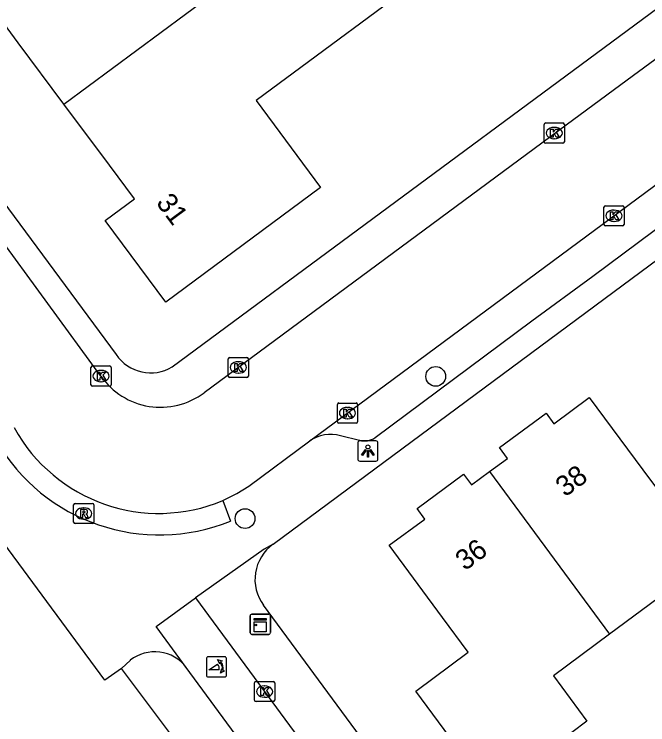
# Model space of a CAD drawing. Extents: x 163427 to 164190, y 380331 to 381641.
# Drawn here: x 163827.17 to 163858.59, y 381170.43 to 381205.64 of the extents above; entities that cross this region are included whole.
import ezdxf

# ---------------------------------------------------------------- set-up
doc = ezdxf.new("R2010")
doc.units = 0
for name, color, linetype in [('IMGEO_Boom', 7, 'Continuous'), ('IMGEO_Fietspad_open', 7, 'Continuous'), ('IMGEO_Groenvoorziening', 7, 'Continuous'), ('IMGEO_Kast', 7, 'Continuous'), ('IMGEO_Kolk', 7, 'Continuous'), ('IMGEO_Lichtpunt', 7, 'Continuous'), ('IMGEO_Pand', 7, 'Continuous'), ('IMGEO_Pand_nummerreeks', 7, 'Continuous'), ('IMGEO_Poller', 7, 'Continuous'), ('IMGEO_Rijbaan_lokaal_open', 7, 'Continuous'), ('IMGEO_Rioolput', 7, 'Continuous'), ('IMGEO_Voetpad_open', 7, 'Continuous')]:
    doc.layers.add(name, color=color, linetype=linetype)

msp = doc.modelspace()

# ---------------------------------------------------------------- linework, layer by layer
at = {"layer": 'IMGEO_Boom'}
for centre in [(163848.072, 381187.697), (163838.62, 381180.647)]:
    msp.add_circle(centre, 0.489, dxfattribs=at)
at = {"layer": 'IMGEO_Fietspad_open'}
for points in [[(163835.703, 381173.277), (163834.212, 381175.298), (163836.166, 381176.725)], [(163836.166, 381176.725), (163851.72, 381155.614), (163849.785, 381154.173), (163848.55, 381155.876)], [(163839.548, 381168.029), (163835.703, 381173.277)]]:
    msp.add_lwpolyline(points, dxfattribs=at)
at = {"layer": 'IMGEO_Groenvoorziening'}
msp.add_lwpolyline([(163837.499, 381166.547), (163832.5, 381173.217)], dxfattribs=at)
at = {"layer": 'IMGEO_Kast'}
for p, q in [((163838.949, 381175.912), (163839.79, 381175.912)), ((163839.79, 381175.912), (163838.949, 381175.912)), ((163838.874, 381174.987), (163838.874, 381175.828)), ((163838.874, 381175.828), (163838.874, 381174.987)), ((163839.874, 381175.837), (163839.874, 381174.996)), ((163839.874, 381174.996), (163839.874, 381175.837)), ((163839.799, 381174.912), (163838.958, 381174.912)), ((163838.958, 381174.912), (163839.799, 381174.912))]:
    msp.add_line(p, q, dxfattribs=at)
for points in [[(163839.069, 381175.702), (163839.669, 381175.702), (163839.669, 381175.617), (163839.069, 381175.617), (163839.069, 381175.702)], [(163839.069, 381175.527), (163839.669, 381175.527), (163839.669, 381175.038), (163839.069, 381175.038), (163839.069, 381175.527)]]:
    msp.add_lwpolyline(points, dxfattribs=at)
msp.add_circle((163839.153, 381175.376), 0.0377, dxfattribs=at)
for centre, start, end in [((163838.952, 381175.834), 92.4484, 184.2845), ((163838.952, 381175.834), 92.4484, 184.2845), ((163839.796, 381175.834), 2.4484, 94.2845), ((163839.796, 381175.834), 2.4484, 94.2845), ((163838.952, 381174.99), 182.4484, 274.2845), ((163838.952, 381174.99), 182.4484, 274.2845), ((163839.796, 381174.99), 272.4484, 4.2845), ((163839.796, 381174.99), 272.4484, 4.2845)]:
    msp.add_arc(centre, 0.0779, start, end, dxfattribs=at)
at = {"layer": 'IMGEO_Kolk'}
for p, q in [((163853.451, 381199.328), (163853.451, 381200.18)), ((163853.526, 381200.254), (163854.378, 381200.254)), ((163854.452, 381200.18), (163854.452, 381199.328)), ((163853.939, 381200.034), (163853.964, 381200.034)), ((163853.962, 381199.474), (163853.937, 381199.474)), ((163854.378, 381199.254), (163853.526, 381199.254)), ((163856.413, 381195.229), (163856.413, 381196.081)), ((163856.488, 381196.155), (163857.34, 381196.155)), ((163857.414, 381196.081), (163857.414, 381195.229)), ((163856.901, 381195.935), (163856.926, 381195.935)), ((163856.924, 381195.375), (163856.899, 381195.375)), ((163857.34, 381195.155), (163856.488, 381195.155)), ((163837.785, 381187.714), (163837.785, 381188.566)), ((163837.86, 381188.64), (163838.712, 381188.64)), ((163838.786, 381188.566), (163838.786, 381187.714)), ((163831.052, 381188.211), (163831.904, 381188.211)), ((163838.273, 381188.42), (163838.298, 381188.42)), ((163830.977, 381187.285), (163830.977, 381188.137)), ((163831.465, 381187.991), (163831.49, 381187.991)), ((163831.978, 381188.137), (163831.978, 381187.285)), ((163838.296, 381187.86), (163838.271, 381187.86)), ((163838.712, 381187.64), (163837.86, 381187.64)), ((163831.904, 381187.211), (163831.052, 381187.211)), ((163831.488, 381187.431), (163831.463, 381187.431)), ((163843.196, 381185.451), (163843.196, 381186.303)), ((163843.271, 381186.377), (163844.123, 381186.377)), ((163843.684, 381186.157), (163843.709, 381186.157)), ((163844.197, 381186.303), (163844.197, 381185.451)), ((163844.123, 381185.377), (163843.271, 381185.377)), ((163843.707, 381185.597), (163843.682, 381185.597)), ((163839.087, 381171.652), (163839.087, 381172.504)), ((163839.162, 381172.578), (163840.014, 381172.578)), ((163839.575, 381172.358), (163839.6, 381172.358)), ((163840.088, 381172.504), (163840.088, 381171.652)), ((163839.598, 381171.798), (163839.573, 381171.798)), ((163840.014, 381171.578), (163839.162, 381171.578))]:
    msp.add_line(p, q, dxfattribs=at)
for points in [[(163853.451, 381199.328), (163853.451, 381200.18)], [(163853.526, 381200.254), (163854.378, 381200.254)], [(163854.452, 381200.18), (163854.452, 381199.328)], [(163853.772, 381199.954), (163853.895, 381199.954), (163853.895, 381199.803), (163854.025, 381199.954), (163854.189, 381199.954), (163854.043, 381199.803), (163854.196, 381199.554), (163854.044, 381199.554), (163853.959, 381199.718), (163853.895, 381199.651), (163853.895, 381199.554), (163853.772, 381199.554), (163853.772, 381199.954)], [(163854.378, 381199.254), (163853.526, 381199.254)], [(163856.413, 381195.229), (163856.413, 381196.081)], [(163856.488, 381196.155), (163857.34, 381196.155)], [(163857.414, 381196.081), (163857.414, 381195.229)], [(163856.734, 381195.855), (163856.857, 381195.855), (163856.857, 381195.704), (163856.987, 381195.855), (163857.151, 381195.855), (163857.005, 381195.704), (163857.158, 381195.455), (163857.006, 381195.455), (163856.921, 381195.619), (163856.857, 381195.552), (163856.857, 381195.455), (163856.734, 381195.455), (163856.734, 381195.855)], [(163857.34, 381195.155), (163856.488, 381195.155)], [(163837.785, 381187.714), (163837.785, 381188.566)], [(163837.86, 381188.64), (163838.712, 381188.64)], [(163838.786, 381188.566), (163838.786, 381187.714)], [(163831.052, 381188.211), (163831.904, 381188.211)], [(163838.106, 381188.34), (163838.229, 381188.34), (163838.229, 381188.189), (163838.359, 381188.34), (163838.523, 381188.34), (163838.377, 381188.189), (163838.53, 381187.94), (163838.378, 381187.94), (163838.293, 381188.104), (163838.229, 381188.037), (163838.229, 381187.94), (163838.106, 381187.94), (163838.106, 381188.34)], [(163830.977, 381187.285), (163830.977, 381188.137)], [(163831.298, 381187.911), (163831.421, 381187.911), (163831.421, 381187.76), (163831.551, 381187.911), (163831.715, 381187.911), (163831.569, 381187.76), (163831.722, 381187.511), (163831.57, 381187.511), (163831.485, 381187.675), (163831.421, 381187.608), (163831.421, 381187.511), (163831.298, 381187.511), (163831.298, 381187.911)], [(163831.978, 381188.137), (163831.978, 381187.285)], [(163838.712, 381187.64), (163837.86, 381187.64)], [(163831.904, 381187.211), (163831.052, 381187.211)], [(163843.196, 381185.451), (163843.196, 381186.303)], [(163843.271, 381186.377), (163844.123, 381186.377)], [(163844.197, 381186.303), (163844.197, 381185.451)], [(163843.517, 381186.077), (163843.64, 381186.077), (163843.64, 381185.926), (163843.77, 381186.077), (163843.934, 381186.077), (163843.788, 381185.926), (163843.941, 381185.677), (163843.789, 381185.677), (163843.704, 381185.841), (163843.64, 381185.774), (163843.64, 381185.677), (163843.517, 381185.677), (163843.517, 381186.077)], [(163844.123, 381185.377), (163843.271, 381185.377)], [(163839.087, 381171.652), (163839.087, 381172.504)], [(163839.162, 381172.578), (163840.014, 381172.578)], [(163840.088, 381172.504), (163840.088, 381171.652)], [(163839.408, 381172.278), (163839.531, 381172.278), (163839.531, 381172.127), (163839.661, 381172.278), (163839.825, 381172.278), (163839.679, 381172.127), (163839.832, 381171.878), (163839.68, 381171.878), (163839.595, 381172.042), (163839.531, 381171.975), (163839.531, 381171.878), (163839.408, 381171.878), (163839.408, 381172.278)], [(163840.014, 381171.578), (163839.162, 381171.578)]]:
    msp.add_lwpolyline(points, dxfattribs=at)
for centre, start, end in [((163853.528, 381200.178), 91.552, 178.448), ((163853.528, 381200.178), 91.552, 178.448), ((163854.376, 381200.178), 1.552, 88.448), ((163854.376, 381200.178), 1.552, 88.448), ((163853.528, 381199.33), 181.552, 268.448), ((163853.528, 381199.33), 181.552, 268.448), ((163854.376, 381199.33), 271.552, 358.448), ((163854.376, 381199.33), 271.552, 358.448), ((163856.49, 381196.079), 91.552, 178.448), ((163856.49, 381196.079), 91.552, 178.448), ((163857.338, 381196.079), 1.552, 88.448), ((163857.338, 381196.079), 1.552, 88.448), ((163856.49, 381195.231), 181.552, 268.448), ((163856.49, 381195.231), 181.552, 268.448), ((163857.338, 381195.231), 271.552, 358.448), ((163857.338, 381195.231), 271.552, 358.448), ((163837.862, 381188.564), 91.552, 178.448), ((163837.862, 381188.564), 91.552, 178.448), ((163838.71, 381188.564), 1.552, 88.448), ((163838.71, 381188.564), 1.552, 88.448), ((163831.054, 381188.135), 91.552, 178.448), ((163831.054, 381188.135), 91.552, 178.448), ((163831.902, 381188.135), 1.552, 88.448), ((163831.902, 381188.135), 1.552, 88.448), ((163837.862, 381187.716), 181.552, 268.448), ((163837.862, 381187.716), 181.552, 268.448), ((163838.71, 381187.716), 271.552, 358.448), ((163838.71, 381187.716), 271.552, 358.448), ((163831.054, 381187.287), 181.552, 268.448), ((163831.054, 381187.287), 181.552, 268.448), ((163831.902, 381187.287), 271.552, 358.448), ((163831.902, 381187.287), 271.552, 358.448), ((163843.273, 381186.301), 91.552, 178.448), ((163843.273, 381186.301), 91.552, 178.448), ((163844.121, 381186.301), 1.552, 88.448), ((163844.121, 381186.301), 1.552, 88.448), ((163843.273, 381185.453), 181.552, 268.448), ((163843.273, 381185.453), 181.552, 268.448), ((163844.121, 381185.453), 271.552, 358.448), ((163844.121, 381185.453), 271.552, 358.448), ((163839.164, 381172.502), 91.552, 178.448), ((163839.164, 381172.502), 91.552, 178.448), ((163840.012, 381172.502), 1.552, 88.448), ((163840.012, 381172.502), 1.552, 88.448), ((163839.164, 381171.654), 181.552, 268.448), ((163839.164, 381171.654), 181.552, 268.448), ((163840.012, 381171.654), 271.552, 358.448), ((163840.012, 381171.654), 271.552, 358.448)]:
    msp.add_arc(centre, 0.0765, start, end, dxfattribs=at)
for centre, major_axis, ratio, start_param, end_param in [((163853.938, 381199.754), (-0.387, 0.002), 0.722429, 4.712389, 7.853982), ((163853.963, 381199.754), (-0.39, 0.002), 0.717154, 1.570796, 4.712389), ((163856.9, 381195.655), (-0.387, 0.002), 0.722429, 4.712389, 7.853982), ((163856.925, 381195.655), (-0.39, 0.002), 0.717154, 1.570796, 4.712389), ((163838.272, 381188.14), (-0.387, 0.002), 0.722429, 4.712389, 7.853982), ((163838.297, 381188.14), (-0.39, 0.002), 0.717154, 1.570796, 4.712389), ((163831.464, 381187.711), (-0.387, 0.002), 0.722429, 4.712389, 7.853982), ((163831.489, 381187.711), (-0.39, 0.002), 0.717154, 1.570796, 4.712389), ((163843.683, 381185.877), (-0.387, 0.002), 0.722429, 4.712389, 7.853982), ((163843.708, 381185.877), (-0.39, 0.002), 0.717154, 1.570796, 4.712389), ((163839.574, 381172.078), (-0.387, 0.002), 0.722429, 4.712389, 7.853982), ((163839.599, 381172.078), (-0.39, 0.002), 0.717154, 1.570796, 4.712389)]:
    msp.add_ellipse(centre, major_axis=major_axis, ratio=ratio, start_param=start_param, end_param=end_param, dxfattribs=at)
at = {"layer": 'IMGEO_Lichtpunt'}
for p, q in [((163844.21, 381184.403), (163844.21, 381183.596)), ((163844.21, 381184.403), (163844.21, 381183.596)), ((163845.112, 381184.498), (163844.304, 381184.498)), ((163845.112, 381184.498), (163844.304, 381184.498)), ((163845.206, 381183.596), (163845.206, 381184.403)), ((163845.206, 381183.596), (163845.206, 381184.403)), ((163844.304, 381183.502), (163845.112, 381183.502)), ((163844.304, 381183.502), (163845.112, 381183.502))]:
    msp.add_line(p, q, dxfattribs=at)
for points in [[(163844.584, 381184.067), (163844.623, 381184.039), (163844.435, 381183.777), (163844.397, 381183.804), (163844.584, 381184.067)], [(163844.686, 381184.019), (163844.733, 381184.019), (163844.733, 381183.697), (163844.686, 381183.697), (163844.686, 381184.019)], [(163844.796, 381184.039), (163844.834, 381184.066), (163845.021, 381183.804), (163844.982, 381183.776), (163844.796, 381184.039)]]:
    msp.add_lwpolyline(points, dxfattribs=at)
msp.add_circle((163844.709, 381184.201), 0.0994, dxfattribs=at)
for centre, start, end in [((163844.304, 381184.403), 90, 180), ((163844.304, 381184.403), 90, 180), ((163845.112, 381184.403), 0, 90), ((163845.112, 381184.403), 0, 90), ((163844.304, 381183.596), 180, 270), ((163844.304, 381183.596), 180, 270), ((163845.112, 381183.596), 270, 0), ((163845.112, 381183.596), 270, 360)]:
    msp.add_arc(centre, 0.0946, start, end, dxfattribs=at)
at = {"layer": 'IMGEO_Pand'}
for points in [[(163829.636, 381201.19), (163845.311, 381212.802)], [(163829.636, 381201.19), (163827.371, 381204.23), (163826.126, 381205.901), (163824.687, 381204.828), (163821.686, 381208.868), (163823.131, 381209.94)], [(163848.469, 381208.26), (163839.171, 381201.361), (163842.364, 381197.057), (163834.696, 381191.367), (163831.69, 381195.418), (163833.135, 381196.495), (163831.894, 381198.16), (163829.636, 381201.19)], [(163850.738, 381182.979), (163851.626, 381183.634), (163851.233, 381184.167), (163853.543, 381185.871), (163853.934, 381185.345), (163855.687, 381186.647), (163858.342, 381183.072), (163859.609, 381181.366), (163862.19, 381183.282), (163863.904, 381180.962), (163865.905, 381178.254), (163861.144, 381174.732), (163859.481, 381176.98), (163856.695, 381174.92)], [(163856.695, 381174.92), (163853.909, 381172.859), (163855.572, 381170.611), (163854.82, 381170.056), (163850.798, 381167.085), (163847.085, 381172.1), (163849.687, 381174.023), (163848.417, 381175.741), (163845.76, 381179.336), (163847.53, 381180.623), (163847.146, 381181.152), (163849.456, 381182.856), (163849.849, 381182.323), (163850.738, 381182.979)], [(163850.738, 381182.979), (163856.695, 381174.92)]]:
    msp.add_lwpolyline(points, dxfattribs=at)
at = {"layer": 'IMGEO_Poller'}
for p, q in [((163837.606, 381173.798), (163836.798, 381173.798)), ((163837.606, 381173.798), (163836.798, 381173.798)), ((163836.704, 381173.703), (163836.704, 381172.896)), ((163836.704, 381173.703), (163836.704, 381172.896)), ((163837.7, 381172.896), (163837.7, 381173.703)), ((163837.7, 381172.896), (163837.7, 381173.703)), ((163836.798, 381172.801), (163837.606, 381172.801)), ((163836.798, 381172.801), (163837.606, 381172.801))]:
    msp.add_line(p, q, dxfattribs=at)
for points in [[(163837.339, 381173.154), (163836.826, 381173.154), (163837.256, 381173.429)], [(163837.383, 381173.527), (163837.371, 381173.454), (163837.246, 381173.659)], [(163837.246, 381173.659), (163837.477, 381173.593), (163837.406, 381173.561)], [(163837.399, 381172.982), (163837.465, 381173.213), (163837.495, 381173.145)], [(163837.531, 381173.118), (163837.603, 381173.107), (163837.399, 381172.982)]]:
    msp.add_lwpolyline(points, dxfattribs=at)
for centre, radius, start, end in [((163836.798, 381173.703), 0.0946, 90, 180), ((163836.798, 381173.703), 0.0946, 90, 180), ((163837.606, 381173.703), 0.0946, 0, 90), ((163837.606, 381173.703), 0.0946, 0, 90), ((163837.011, 381173.204), 0.332, 351.3247, 42.4854), ((163837.025, 381173.214), 0.476, 351.7527, 41.1691), ((163837.025, 381173.214), 0.516, 349.3569, 42.2912), ((163836.798, 381172.896), 0.0946, 180, 270), ((163836.798, 381172.896), 0.0946, 180, 270), ((163837.606, 381172.896), 0.0946, 270, 0), ((163837.606, 381172.896), 0.0946, 270, 0)]:
    msp.add_arc(centre, radius, start, end, dxfattribs=at)
at = {"layer": 'IMGEO_Rijbaan_lokaal_open'}
for points in [[(163831.473, 381187.71), (163826.186, 381194.912), (163822.567, 381199.76), (163818.169, 381205.736), (163815.921, 381208.742), (163811.56, 381214.644), (163809.355, 381217.654), (163805.5, 381222.854), (163803.25, 381225.899), (163797.56, 381233.618)], [(163871.192, 381212.44), (163866.121, 381208.698), (163863.127, 381206.47), (163857.562, 381202.374), (163854.549, 381200.154), (163836.589, 381186.888)], [(163841.832, 381184.499), (163872.997, 381207.555)], [(163837.52, 381181.547), (163838.212, 381181.888), (163838.806, 381182.261), (163841.832, 381184.499)]]:
    msp.add_lwpolyline(points, dxfattribs=at)
for centre, radius, start, end in [((163834.427, 381189.762), 3.597, 214.7878, 306.9565), ((163834.349, 381189.098), 8.19, 208.7726, 292.7771)]:
    msp.add_arc(centre, radius, start, end, dxfattribs=at)
at = {"layer": 'IMGEO_Rioolput'}
for p, q in [((163830.117, 381180.476), (163830.117, 381181.328)), ((163830.192, 381181.402), (163831.044, 381181.402)), ((163830.605, 381181.182), (163830.63, 381181.182)), ((163831.118, 381181.328), (163831.118, 381180.476)), ((163830.628, 381180.622), (163830.603, 381180.622)), ((163831.044, 381180.402), (163830.192, 381180.402))]:
    msp.add_line(p, q, dxfattribs=at)
for points in [[(163830.117, 381180.476), (163830.117, 381181.328)], [(163830.192, 381181.402), (163831.044, 381181.402)], [(163831.118, 381181.328), (163831.118, 381180.476)], [(163830.706, 381181.1), (163830.454, 381181.102), (163830.454, 381180.702)], [(163830.454, 381180.702), (163830.578, 381180.702), (163830.578, 381180.864), (163830.589, 381180.864)], [(163830.632, 381181.021), (163830.578, 381181.021), (163830.578, 381180.94)], [(163830.578, 381180.94), (163830.63, 381180.94)], [(163830.636, 381180.835), (163830.707, 381180.702), (163830.847, 381180.702), (163830.782, 381180.828)], [(163831.044, 381180.402), (163830.192, 381180.402)]]:
    msp.add_lwpolyline(points, dxfattribs=at)
for centre, radius, start, end in [((163830.194, 381181.326), 0.0765, 91.552, 178.448), ((163830.194, 381181.326), 0.0765, 91.552, 178.448), ((163831.042, 381181.326), 0.0765, 1.552, 88.448), ((163831.042, 381181.326), 0.0765, 1.552, 88.448), ((163830.588, 381180.811), 0.0533, 26.0293, 88.6989), ((163830.614, 381181.129), 0.19, 274.7715, 282.9687), ((163830.638, 381180.925), 0.0964, 77.0061, 93.1865), ((163830.652, 381180.982), 0.0378, 276.6634, 79.6772), ((163830.705, 381180.99), 0.109, 350.3612, 89.416), ((163830.703, 381180.99), 0.112, 277.5842, 350.9817), ((163830.687, 381180.775), 0.108, 29.5134, 73.7905), ((163830.194, 381180.478), 0.0765, 181.552, 268.448), ((163830.194, 381180.478), 0.0765, 181.552, 268.448), ((163831.042, 381180.478), 0.0765, 271.552, 358.448), ((163831.042, 381180.478), 0.0765, 271.552, 358.448)]:
    msp.add_arc(centre, radius, start, end, dxfattribs=at)
for centre, major_axis, ratio, start_param, end_param in [((163830.604, 381180.902), (-0.387, 0.002), 0.722429, 4.712389, 7.853982), ((163830.629, 381180.902), (-0.39, 0.002), 0.717154, 1.570796, 4.712389)]:
    msp.add_ellipse(centre, major_axis=major_axis, ratio=ratio, start_param=start_param, end_param=end_param, dxfattribs=at)
at = {"layer": 'IMGEO_Voetpad_open'}
for points in [[(163832.5, 381173.217), (163831.667, 381172.644), (163783.277, 381238.221), (163784.4, 381239.055), (163784.841, 381239.434)], [(163798.704, 381234.11), (163801.193, 381230.722), (163832.228, 381188.776)], [(163835.008, 381188.174), (163876.336, 381218.714)], [(163840.007, 381179.376), (163875.112, 381205.371)], [(163871.857, 381204.539), (163855.86, 381192.644), (163852.834, 381190.43), (163845.069, 381184.659)], [(163844.299, 381184.527), (163843.344, 381184.751)], [(163837.52, 381181.547), (163837.901, 381180.526)], [(163840.007, 381179.376), (163839.561, 381179.132), (163836.166, 381176.725)], [(163875.058, 381130.776), (163855.129, 381157.768), (163853.96, 381156.776), (163839.528, 381176.358)], [(163832.5, 381173.217), (163832.93, 381173.629)]]:
    msp.add_lwpolyline(points, dxfattribs=at)
for centre, radius, start, end in [((163833.931, 381189.92), 2.052, 213.8985, 301.6643), ((163842.847, 381183.07), 1.753, 73.5395, 125.3851), ((163834.382, 381189.197), 9.358, 210.1354, 292.0882), ((163844.538, 381185.445), 0.948, 255.4066, 304.0485), ((163841.252, 381177.631), 2.143, 125.5033, 216.4599), ((163834.142, 381172.079), 1.968, 37.5043, 128.0271)]:
    msp.add_arc(centre, radius, start, end, dxfattribs=at)

# ---------------------------------------------------------------- texts
at = {"layer": 'IMGEO_Pand_nummerreeks'}
for s, rotation, p in [('31', 306.5717, (163834.173, 381196.3)), ('38', 36.3714, (163854.488, 381181.689)), ('36', 36.3714, (163849.521, 381178.033))]:
    msp.add_text(s, height=1, rotation=rotation, dxfattribs=at).set_placement(p)

doc.saveas('drawing.dxf')
